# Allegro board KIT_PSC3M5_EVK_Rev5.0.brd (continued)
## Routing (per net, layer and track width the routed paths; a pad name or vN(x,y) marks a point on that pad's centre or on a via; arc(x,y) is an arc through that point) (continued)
USB_V_SENSE: length 5.2
  TOP w0.157: U2.19 92.66,35.27 92.89,35.05 v1(92.89,33.3)
  BOTTOM w0.157: R81.2 R79.2 94.13,33.81 93.62,33.3 v1(92.89,33.3)
USER_SWITCH: length 71.6
  TOP w0.178: R158.1 98.44,44.26 v1(98.63,44.45) ; SW2.B v1(44.53,57.81)
  L04_SIG2 w0.178: v1(44.53,57.81) 47.93,57.81 v1(50.93,54.81)
  BOTTOM w0.178: v1(50.93,54.81) 56.11,54.81 58.68,57.39 62.63,57.39 64.08,55.94 96.16,55.94 98.63,53.47 v1(98.63,44.45) ; R44.2 43.08,57.91 43.13,57.86 C43.1 44.48,57.86 v1(44.53,57.81)
VAREF_EXT: length 8.1
  TOP w0.292: 58.55,32.66 58.64,32.76 U1.65
  TOP w0.381: 58.55,32.66 58.24,32.36 C37.1 57.3,31.44 v1(56.79,31.95)
  BOTTOM w0.508: v1(56.79,31.95) 56.54,31.95 56.03,31.45 R92.2 R93.2
VBACKUP: length 5.3
  TOP w0.292: U1.11 v1(66.59,41.58)
  BOTTOM w0.508: v1(66.59,41.58) 66.49,41.68 C50.1 65.78,41.19 65.93,41.05 C53.1 R69.1
VOUT_3V3: length 27.9
  TOP w0.381: 116.71,19.41 J17.2 ; J17.2 118.65,19.41 ; J17.2 117.68,18.44 ; U9.3 70.55,25.14 ; U9.3 69.25,24.38 ; U9.3 71.85,24.38 ; U9.3 70.55,23.63 ; C97.1 76.03,23.1 ; C97.1 75.31,23.77 ; C97.1 74.59,23.1 ; C98.1 73.41,23.92 ; C98.1 72.46,23.12 ; C98.1 74.35,23.12
  TOP w1.016: v1(78.41,22.86) v1(77.44,22.86)
  L03_SIG1 w0.381: 117.68,18.44 J17.2 ; J17.2 118.65,19.41 ; J17.2 116.71,19.41
  L03_SIG1 w1.016: TP10.1 46.74,19.81 46.76,19.79
  BOTTOM w0.305: U5.1 86.61,32.03 C61.1
  BOTTOM w0.381: 87.37,32.26 C61.1 86.84,32.75 ; 72.05,17.38 Q7.1 72.51,16.97 ; 73.93,15.84 Q5.D ; Q5.D 73.26,16.46 ; Q5.D 73.93,17.08 ; 73.64,13.79 R141.1 ; R141.1 74.31,13.07 ; R141.1 74.31,14.51 ; v1(125.43,19.18) 125.49,19.11 R116.1 ; 77.78,33.08 R156.2 77.06,32.42
  vias: v1(52.1,24.16) v1(52.1,22.25) v1(53.11,23.27) v1(54,24.16) v1(54,22.25) v1(73,13.16) v1(73.3,13.74) v1(73.66,12.85) v1(78.16,33.05) v1(78.44,32.39) v1(87.66,31.19) v1(87.66,30.56)
VOUT_5V0: length 41
  TOP w0.292: U4.3 39.41,14.08
  TOP w0.381: 69.25,19.3 U9.1 ; U9.1 71.85,19.3 ; U9.1 70.55,18.55 ; 74.15,18.44 C95.1 ; C95.1 74.68,17.94 ; C95.1 75.2,18.44 ; 57.49,10.57 TP12.1 58.57,11.64 ; 40.29,13.24 C41.2 39.52,13.97 39.41,14.08 ; 72.62,18.44 C96.1 ; C96.1 73.68,18.44 ; C96.1 73.15,17.94
  L04_SIG2 w0.508: v1(92.61,16.69) 91.49,17.81 90.07,17.81 v1(89.23,18.64) 89.08,18.8 89.08,22.68 v1(89.43,23.04)
  BOTTOM w0.381: C83.1 90.17,21.81 ; C83.1 89.64,21.31 ; C83.1 90.7,21.31 ; C86.1 86.87,22.39 ; C86.1 85.92,21.6 ; C86.1 87.81,21.6 ; 83.63,13.23 R143.1 ; R143.1 82.94,14.15 ; R143.1 83.63,15.07 ; R123.1 89.29,18.59 v1(89.23,18.64) 89.23,18.36 C91.1 ; 81.26,17.45 Q6.1 ; Q6.1 81.72,17.86 ; Q6.1 82.19,17.45 ; C85.1 89.49,21.45 ; C85.1 88.77,22.12 ; C85.1 88.05,21.45 ; C87.1 84.71,22.39 ; C87.1 83.77,21.6 ; C87.1 85.65,21.6 ; C88.1 83.23,21.46 ; C88.1 82.43,22.41 ; C88.1 82.43,20.52 ; R126.1 v1(92.61,16.69) ; 91,21.35 U8.7 ; 91.05,21.58 U8.8 ; 83.02,16.99 Q4.D ; Q4.D 83.68,16.37 ; Q4.D 83.68,17.61
  vias: v1(74.42,17.78) v1(75.06,17.78) v1(75.44,18.42)
VREFH: length 25.8
  TOP w0.381: 65.02,57.98 J3.8 ; J3.8 66.1,59.05 ; J3.8 65.02,60.13 ; J3.8 63.95,59.05
  TOP w0.508: v1(63.78,10.57) 64.13,10.22 v1(64.64,10.22) 65.91,10.22 69.85,6.27 69.85,4.5 70.54,3.81 77.47,3.81 J24.15
  L04_SIG2 w0.635: v1(55.91,28.22) v1(56.67,28.22)
  BOTTOM w0.381: 56.75,29.37 R92.1 56.03,28.71
VTARG_DEBUG: length 14.9
  TOP w0.381: 124.95,44.32 J11.1 ; J11.1 126.36,43.72 ; J11.1 127.78,44.32
  L05_PWR w0.381: 109.57,38.61 J14.1 108.33,37.86
  BOTTOM w0.381: R147.2 65.92,12.45 ; C52.1 125.73,41.07 ; C52.1 125.73,40.01 ; C52.1 125.23,40.54 ; Q9.4 61.17,14.07 v1(61.34,13.89) ; 66.15,13.54 Q8.S ; Q8.S 66.82,14.16 ; Q8.S 66.15,14.78 ; 125.18,41.96 D1.K ; D1.K 125.7,41.35 ; D1.K 125.7,42.57
  BOTTOM w0.508: R60.2 v1(117.02,44.22) ; R52.2 v1(117.02,48.16) ; R59.2 v1(117.02,45.87)
  vias: v1(66.52,12.34) v1(66.83,12.88) v1(124.38,43.1) v1(124.89,43.43) v1(124.89,42.72)
VTARG_MEAS: length 3
  TOP w0.191: v1(93.24,40.92) 92.79,40.47 U2.32
  BOTTOM w0.381: R66.2 R67.2 94.22,40.92 v1(93.24,40.92)
VTARG_REF: length 62.1
  TOP w0.762: R41.1 84.94,24.37 v1(84.94,23.9) ; LED1.A v1(26.85,55.93) ; LED2.A v1(26.82,52.63)
  L03_SIG1 w1.016: v1(110.52,25.55) v1(110.52,24.54) 110.52,14.88 115.34,10.06 123.93,10.06 v1(125.27,11.4)
  L05_PWR w0.381: 70.55,10.79 J1.7 ; J1.7 71.63,9.72 ; J1.7 72.71,10.79
  BOTTOM w0.229: U5.4 83.19,32.03
  BOTTOM w0.381: 71.63,9.72 J1.7 ; J1.7 71.63,11.87 ; J1.7 72.71,10.79 ; J1.7 70.55,10.79 ; 63.75,11.73 R147.1 ; R147.1 64.42,12.45 ; R147.1 63.75,13.16 ; R128.1 v1(52.46,18.17) ; R57.2 50.47,48.54 v1(50.7,48.77) ; 62.32,15.55 Q9.1 62.79,15.14 ; C58.1 82.68,33.07 ; C58.1 v1(82.17,33.91) ; C58.1 82.17,32.54 ; v1(125.27,11.4) R150.2 125.27,12.88 125.36,12.98 Q10.G ; 64.15,14.49 Q8.D ; Q8.D 64.15,15.73 ; Q8.D 63.48,15.11 ; R50.2 87.63,49.07 v1(87.4,49.3) ; v1(94.39,43.31) 94.23,43.15 R66.1 ; R76.1 v1(74.45,34.57) ; R64.2 v1(49.56,42.99) ; U5.4 83.73,32.39 ; R73.1 v1(74.57,36.09) ; R153.1 v1(52.46,8.39) ; v1(85.24,49.3) 85.01,49.07 R51.2 ; R61.1 v1(85.98,45.24)
  BOTTOM w0.508: v1(31.39,16.66) R131.2 v1(32.3,17.67) ; R43.1 v1(51.59,63.27) ; v1(72.03,28.47) 72.26,28.24 R107.2
  vias: v1(64.16,11.46) v1(64.8,11.46) v1(82.83,33.93)
VTARG_REF_EN: length 5.6
  BOTTOM w0.381: R86.2 80.14,30.48 79.22,31.4
  BOTTOM w0.635: R157.1 R156.1 79.03,31.58 79.22,31.4
WCO_IN: length 5.1
  TOP w0.178: R22.1 72.43,42.84 72.17,42.58 U1.13
WCO_OUT: length 6.6
  TOP w0.178: R26.1 73.57,41.29 72.78,42.08 U1.12
XRES_L_MCU: length 335.3
  TOP w0.178: v1(102.86,44.45) R25.1 104.67,43.43 104.93,43.69 J14.10 ; J11.10 v1(120.73,49.4) ; SW1.A v1(32.38,24.43) 31.52,25.3 11.46,25.3 J16.2 ; U1.8 68.99,40.08 69.6,39.47 v1(69.62,39.47)
  L03_SIG1 w0.157: v1(120.73,49.4) 120.73,50.6 118.11,53.21 105.36,53.21 102.86,50.71 v1(102.86,44.45) ; J1.6 72.44,9.07 57.91,9.07 56.72,10.26 15.77,10.26 J18.3 9.53,16.51 J16.2 ; v1(69.62,39.47) 68.28,39.47 67.55,40.2 58.74,40.2 v1(58.19,39.65)
  L04_SIG2 w0.157: v1(102.86,44.45) 98.95,48.36 83.26,48.36 82.09,49.53 76,49.53 74.57,48.11 71.88,48.11 69.42,45.64 69.42,39.67 v1(69.62,39.47) 74.9,39.47 81.28,33.1 84.81,33.1 85.42,32.49 88.44,32.49 89.43,31.5 89.43,25.81 85.78,22.15 83.85,22.15 78.26,16.56 78.26,14.88 J1.6 ; J5.30 72.42,63.53 60.86,63.53 56.9,59.56 56.9,52.98 54.1,50.19 54.1,42.21 56.67,39.65 v1(58.19,39.65) ; J16.2 9.53,33.66 15.74,39.87 15.74,47.48 9.55,53.67 9.55,58.93 10.79,60.17 J6.3
  BOTTOM w0.178: C67.1 31.58,25.23 31.65,25.3 R109.2 32.28,24.54 v1(32.38,24.43)
N22087450: length 2.3
  TOP w0.191: U2.53 83.64,40.87 83.49,40.72
  TOP w0.381: 83.49,40.72 C12.1
N22087778: length 2.1
  TOP w0.191: U2.42 88.69,42.84 88.72,42.88
  TOP w0.381: 88.72,42.88 89.15,43.31 C5.1
N22087991: length 4
  TOP w0.114: U2.22 92.76,36.47 92.84,36.56 92.94,36.56 93.91,35.59 94.23,35.59 v1(94.51,35.31)
  BOTTOM w0.114: R75.2 95.33,35.27 95.01,35.6 94.8,35.6 v1(94.51,35.31)
N22087993: length 4
  TOP w0.114: U2.23 92.75,36.87 92.83,36.79 93.03,36.79 94.01,35.81 94.21,35.81 v1(94.51,36.12)
  BOTTOM w0.114: R72.2 95.33,36.18 94.98,35.83 94.8,35.83 v1(94.51,36.12)
N22088003: length 2.1
  TOP w0.191: U2.31 93.03,40.07
  TOP w0.381: 93.03,40.07 93.24,40.28 C13.1
N22088231: length 2.5
  TOP w0.178: LED3.A v1(114.39,25.55)
  BOTTOM w0.178: R106.1 114.55,25.71 v1(114.39,25.55)
N22092982: length 7.5
  L04_SIG2 w0.508: v1(65.3,15.27) 64.59,15.27 62.89,13.56 v1(62.89,12.85)
  BOTTOM w0.381: Q9.3 62.32,13.68 62.15,13.51 R146.1 62.74,12.7 v1(62.89,12.85) ; v1(65.3,15.27) 65.3,15.68 65.68,16.06 Q8.G
N22093014: length 3.2
  BOTTOM w0.292: R142.2 59.66,14.61 Q9.5 Q9.2
N22093052: length 1.4
  BOTTOM w0.292: R138.1 59.58,15.14 Q9.6
N22129895: length 6.6
  TOP w0.178: Y2.2 78.73,40.85 C10.2 76.68,40.85 76.35,41.17 76.35,42.32 75.21,43.46 R22.2
N22129929: length 4.6
  TOP w0.178: R18.1 74.96,45.36 C7.2 77.38,45.17 Y1.3
N22129931: length 5.1
  TOP w0.178: Y1.1 77.75,47.73 C3.1 74.96,47.14 R14.2
N22129945: length 4.1
  TOP w0.178: R26.2 75.72,40.54 76.61,39.65 C16.2 78.73,39.65 Y2.1
N22154314: length 2.3
  TOP w0.292: J15.A5 v1(121.57,28.6)
  BOTTOM w0.292: v1(121.57,28.6) 121.55,28.57 R99.1
N22154327: length 2.4
  TOP w0.292: J15.B5 v1(121.11,31.6)
  BOTTOM w0.292: v1(121.11,31.6) 120.59,31.6 R83.1
N22156925: length 6.2
  BOTTOM w0.33: 93.75,22.73 93.46,22.45 U8.11
  BOTTOM w0.381: 94.46,23.36 L1.1 ; L1.1 94.46,27.49 ; L1.1 95.23,25.43
N22156929: length 6.1
  BOTTOM w0.33: U8.9 92.46,22.55 92.25,22.76
  BOTTOM w0.381: 90.7,25.43 L1.2 ; L1.2 91.46,23.36 ; L1.2 91.46,27.49
N22157101: length 2.8
  BOTTOM w0.254: U8.14 94.97,20.58 95.22,20.32 95.22,19.74 95.74,19.22 R121.1
N22157103: length 5.7
  TOP w0.191: v1(93.6,16.15) 93.62,16.13 TP11.1
  BOTTOM w0.216: R126.2 93,18.18 93.22,17.96 93.22,16.53 v1(93.6,16.15)
  BOTTOM w0.254: R126.2 92.61,18.57 93.21,19.17 U8.2
N22157131: length 2.6
  BOTTOM w0.254: U8.1 93.71,18.77 93.8,18.68 R125.2 R124.2
N22157141: length 2.1
  BOTTOM w0.254: U8.3 92.71,19.33 91.52,18.13 C90.1
N22157156: length 5.6
  BOTTOM w0.254: U8.5 91.4,20.08 91.21,19.89 91.21,19.3 90.67,18.76 90.67,17.95 90.46,17.74 R123.2 R134.2
  BOTTOM w0.381: R134.2 89.01,16.81 88.93,16.89 88.83,16.89 C91.2
N22173555: length 5.2
  TOP w0.178: R35.1 36.57,34.48 C25.2 38.12,34.48 R36.2 40.26,34.47 TP5.1
N22173666: length 5.4
  TOP w0.178: C1.2 35.2,53.98 R5.1 R6.2 37.11,53.89 TP3.1
N22184104: length 7.2
  L04_SIG2 w0.508: v1(84.61,18.19) 82.19,15.77 v1(82.19,15.14)
  BOTTOM w0.292: 81.72,15.9 Q6.3
  BOTTOM w0.381: 81.72,15.9 81.55,15.73 R139.1 v1(82.19,15.14)
  BOTTOM w0.508: v1(84.61,18.19) 84.85,17.94 Q4.G
N22184124: length 8.6
  L04_SIG2 w0.508: v1(76.84,17.92) 75.2,16.28 74.19,16.28 v1(72.8,14.88)
  BOTTOM w0.292: 72.05,15.27 Q7.3
  BOTTOM w0.381: v1(72.8,14.88) 72.57,14.66 R140.1 72,15.22 72.05,15.27
  BOTTOM w0.508: v1(76.84,17.92) 76.44,17.92 Q5.G
N22184135: length 3.2
  BOTTOM w0.292: R133.2 79.22,16.92 Q6.5 Q6.2
N22184141: length 3.3
  BOTTOM w0.292: R135.2 69.69,16.43 Q7.5 Q7.2
N22184147: length 1.3
  BOTTOM w0.292: R127.1 79.38,17.48 79.4,17.45 Q6.6
N22184151: length 1.3
  BOTTOM w0.292: Q7.6 69.5,16.97 69.37,16.84 R130.1
N22185312: length 11.1
  TOP w0.178: v1(123.16,57.12) 121.85,55.82 R2.1
  BOTTOM w0.178: v1(123.16,57.12) C42.1 123.16,61.19 R1.2
N22190096: length 120.3
  TOP w0.203: v1(52.98,65.81) 52.81,65.99 SW4.A
  L04_SIG2 w0.157: v1(103.02,62.26) 104.42,62.26 106.2,60.48 106.2,57.05 105.31,56.16 105.31,27.08 111.79,20.6 111.79,9.04 109.6,6.86 108.46,6.86 J24.38
  BOTTOM w0.178: v1(103.02,62.26) 102.51,62.76 59.84,62.76 56.23,66.38 R160.1 53.55,66.38 v1(52.98,65.81)
  BOTTOM w0.203: R43.2 52.97,65.8 v1(52.98,65.81)
N22190335: length 2.5
  TOP w0.178: LED2.K v1(29.75,51.33)
  BOTTOM w0.178: v1(29.75,51.33) 29.92,51.5 R46.1
N22190371: length 2.2
  TOP w0.178: LED1.K v1(29.75,57.16)
  BOTTOM w0.178: v1(29.75,57.16) 29.95,56.97 R45.1
N22190519: length 3.3
  BOTTOM w0.178: R128.2 53.31,14.19 J19.1
N22190521: length 3.3
  BOTTOM w0.178: J22.1 53.31,4.41 R153.2
N22190557: length 3.3
  BOTTOM w0.178: J19.3 48.1,14.23 R129.1
N22190561: length 3.3
  BOTTOM w0.178: R154.1 48.1,4.45 J22.3
N22191822: length 3.8
  BOTTOM w0.305: U5.3 83.06,31.53 82.92,31.67 R155.2 81.31,31.67 C62.1 81.28,31.04 81.32,30.99 R86.1
N22248472: length 6.9
  TOP w0.178: J13.S R32.1
N22248626: length 8.9
  TOP w0.178: R4.1 33.68,57.18 35.08,58.57 J7.S
N22257092: length 12.2
  TOP w0.178: v1(32.95,11.68) 32.95,12.37 v1(34.44,13.87) 34.66,14.08 U4.6 ; v1(33,8.79) 33,6.43 32.13,5.56 J23.1
  BOTTOM w0.178: v1(32.95,11.68) C94.2 33,10.77 R152.1 v1(33,8.79) ; R144.1 v1(34.44,13.87)
N22257130: length 12.1
  TOP w0.178: v1(33.91,11.68) 33.91,12.19 v1(34.44,12.73) 34.44,13.06 34.81,13.43 U4.7 ; v1(33.85,8.79) 33.85,8.08 34.03,7.9 34.42,7.9 34.59,7.72 34.59,7.37 34.42,7.19 34.03,7.19 33.85,7.01 33.85,6.38 34.67,5.56 J23.2
  BOTTOM w0.178: v1(33.85,8.79) R152.2 33.85,10.77 C94.1 v1(33.91,11.68) ; R145.2 v1(34.44,12.73)
N22257140: length 2.3
  BOTTOM w0.178: R144.2 R145.1 C93.1
N22258155: length 2.1
  TOP w0.178: U4.1 39.08,12.78 v1(39.52,12.34)
  BOTTOM w0.178: R149.1 v1(39.52,12.34)
N22258259: length 2.2
  TOP w0.178: v1(39.52,15.01) 39.24,14.73 U4.4
  BOTTOM w0.178: R137.1 39.9,15.39 v1(39.52,15.01)
N22258799: length 5.3
  BOTTOM w0.381: Q1.S 104.64,30.95 ; Q1.S 104.02,31.42 ; Q1.S 104.02,30.48 ; 103.97,28.44 Q3.S 104.44,27.82 ; 107.74,30.73 Q2.S 107.12,31.2 ; 105.41,31.24 R84.2 ; R84.2 105.94,30.74 ; R84.2 106.47,31.24
N22258824: length 4
  BOTTOM w0.381: R98.2 102.05,29.98 ; R98.2 102.47,29.49 ; R98.2 102.05,29 ; 102.54,27.82 Q3.G 102.07,28.44 ; Q1.D 102.64,31.9 ; Q1.D 102.02,32.37 ; Q1.D 102.02,31.43
N22258828: length 7.9
  BOTTOM w0.381: D2.K 106.1,33.1 105.94,32.94 R84.1 ; D2.K 105.26,34.44 ; D2.K 106.1,35.66 ; R84.1 105.34,32.32 104.8,32.85 Q1.G ; R84.1 106.47,32.32 ; Q1.G 104.02,33.32 ; Q1.G 104.02,32.38
N22307724: length 2.2
  TOP w0.178: LED4.K 124.78,16.83 v1(124.71,16.76)
  BOTTOM w0.178: Q10.D v1(124.71,16.76)
N223077121: length 2.4
  TOP w0.178: LED4.A v1(126.58,19.25)
  BOTTOM w0.178: R116.2 126.57,18.59 126.58,18.59 v1(126.58,19.25)

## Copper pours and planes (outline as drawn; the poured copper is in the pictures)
GND_EARTH on BOTTOM: 128.93,36.73 127.91,37.74 122.45,37.74 121.64,36.93 121.64,33.22 122.33,32.54 122.33,23.65 121.95,23.27 121.95,20.85 122.2,20.6 128.42,20.6 128.93,21.11
GND_SIGNAL on TOP (solid shape): 16.73,50.48 15.02,50.48 15.02,54.36 16.73,54.36
GND_SIGNAL on TOP (solid shape): 16.73,1.2 15.02,1.2 15.02,5.08 16.73,5.08
GND_SIGNAL on TOP (solid shape): 121.92,33.32 123.01,33.32 123.16,33.17 123.16,32.87 123.11,32.82 120.8,32.82 120.52,33.1 120.52,33.58 120.68,33.73 121.51,33.73
GND_SIGNAL on TOP (solid shape): 123.16,26.82 123.16,26.47 123.06,26.37 122.02,26.37 121.74,26.09 120.93,26.09 120.85,26.16 120.85,26.82 120.93,26.9 123.09,26.9
GND_SIGNAL on TOP: 128.98,2.54 128.54,1.46 127.46,1.02 2.54,1.02 1.46,1.46 1.02,2.54 1.02,67.46 1.46,68.54 2.54,68.98 127.46,68.98 128.54,68.54 128.98,67.46 ; 50 cut-outs
GND_SIGNAL on BOTTOM: 128.98,2.54 128.54,1.46 127.46,1.02 2.54,1.02 1.46,1.46 1.02,2.54 1.02,67.46 1.46,68.54 2.54,68.98 127.46,68.98 128.54,68.54 128.98,67.46 ; 21 cut-outs
GND_SIGNAL on L02_GND: 128.98,2.54 128.54,1.46 127.46,1.02 2.54,1.02 1.46,1.46 1.02,2.54 1.02,67.46 1.46,68.54 2.54,68.98 127.46,68.98 128.54,68.54 128.98,67.46
VCC_IN on BOTTOM: 94.08,20.98 96.82,20.98 97.13,21.29 103.35,21.29 104.37,20.27 104.37,18.39 104.09,18.11 97.08,18.11 96.65,18.54 95,18.54 94.64,18.19 94.64,16.41 95.15,15.9 101.88,15.9 103.28,14.5 107.21,14.5 107.85,15.14 107.85,23.52 107.34,24.03 97.28,24.03 95.73,22.48 94.41,22.48 94.08,22.15
VDD_POT on BOTTOM: 114.71,54.64 122.2,62.13 126.01,62.13 127.03,63.14 127.03,64.8 126.19,65.63 118.69,65.63 112.52,59.46 112.52,54.79 112.67,54.64
VDDA on BOTTOM: 111.71,60.45 109.93,60.45 109.42,59.94 109.42,54.86 109.8,54.48 111.84,54.48 112.09,54.74 112.09,60.07
VDDA on BOTTOM: 55.02,29.74 53.49,29.74 53.49,28.85 53.37,28.73 44.98,28.73 44.6,29.11 44.6,41.55 44.22,41.94 40.79,41.94 40.16,41.3 40.16,26.82 41.61,25.37 54.33,25.37 55.14,26.19 55.14,29.62
VDDA on L04_SIG2: 59.97,33.93 53.75,33.93 53.24,33.43 53.24,27.84 53.49,27.58 54.89,27.58 55.14,27.84 55.14,29.11 56.92,30.89 60.1,30.89 60.6,31.39 60.6,33.3
VDDA on L05_PWR: 61.62,56.54 53.87,64.29 50.62,64.29 50.01,63.68 50.01,56.26 50.85,55.42 50.85,50.24 48.67,48.06 48.67,38.25 47.78,37.36 42.95,37.36 42.32,38 42.32,41.94 43.08,42.7 43.08,65.56 45.49,67.97 84.76,67.97 90.25,62.48 107.37,62.48 108.41,61.44 112.17,61.44 112.65,60.96 112.65,57 112.19,56.54
VDDD on L05_PWR: 42.44,57.05 39.27,57.05 38.73,56.52 38.73,35.05 31.9,28.22 31.9,26.7 32.41,26.19 35.59,26.19 42.57,33.17 56.16,33.17 62.51,39.52 70.76,39.52 71.15,39.9 71.15,41.3 69.75,42.7 58.95,42.7 53.24,36.98 43.97,36.98 42.65,38.3 42.65,56.84
VDDIO_0 on BOTTOM: 55.02,50.57 53.75,50.57 53.62,50.44 53.62,43.46 52.48,42.32 50.19,42.32 49.81,41.94 49.81,40.92 57.45,40.92 59.08,42.55 68.61,42.55 69.52,43.46 72.24,43.46 73.69,44.91 73.69,46.76 73.3,47.14 56.29,47.14 55.4,48.03 55.4,50.19
VIN on TOP: 99.97,17.3 98.7,17.3 98.32,16.92 98.32,13.87 98.58,13.61 100.23,13.61 100.48,13.87 100.48,16.79
VIN on BOTTOM: 117.17,9.75 114.71,9.75 114.1,10.36 114.1,15.72 113.61,16.21 112.47,16.21 111.58,17.09 109.45,17.09 109.27,16.92 109.27,14.78 108.61,14.12 102.64,14.12 101.37,15.39 99.21,15.39 98.7,14.88 98.7,12.34 99.09,11.96 110.44,11.96 110.9,11.51 110.9,5.36 111.71,4.55 117.32,4.55 117.63,4.85 117.63,9.3
VIN_EXP on TOP: 61.42,13.41 59.08,11.07 59.08,4.34 59.72,3.71 62.38,3.71 63.02,4.34 63.02,9.93 63.88,10.8 73.15,10.8 79.68,17.32 86.23,17.32 87.58,15.98 87.58,13.28 87.12,12.83 86.18,12.83 85.5,12.14 85.5,9.68 85.75,9.42 89.81,9.42 90.22,9.83 90.22,11.61 91.59,12.98 96.8,12.98 97.43,13.61 97.43,20.22 96.75,20.9 79.2,20.9 71.7,13.41
(no net) on L03_SIG1: 128.98,2.54 128.54,1.46 127.46,1.02 2.54,1.02 1.46,1.46 1.02,2.54 1.02,67.46 1.46,68.54 2.54,68.98 127.46,68.98 128.54,68.54 128.98,67.46 ; 93 cut-outs
(no net) on L04_SIG2: 128.98,2.54 128.54,1.46 127.46,1.02 2.54,1.02 1.46,1.46 1.02,2.54 1.02,67.46 1.46,68.54 2.54,68.98 127.46,68.98 128.54,68.54 128.98,67.46 ; 73 cut-outs
ARD_A4 on TOP (solid shape): 6.57,50.48 4.86,50.48 4.86,54.36 6.57,54.36
ARD_A4 on TOP (solid shape): 6.57,1.2 4.86,1.2 4.86,5.08 6.57,5.08
ARD_A5 on TOP (solid shape): 9.11,50.48 7.4,50.48 7.4,54.36 9.11,54.36
ARD_A5 on TOP (solid shape): 9.11,1.2 7.4,1.2 7.4,5.08 9.11,5.08
HDR_3V3 on TOP (solid shape): 19.27,50.48 17.56,50.48 17.56,54.36 19.27,54.36
HDR_3V3 on TOP (solid shape): 19.27,1.2 17.56,1.2 17.56,5.08 19.27,5.08
HDR_3V3 on BOTTOM: 70.64,16.03 69.62,16.03 69.49,15.9 69.49,14.63 69.75,14.38 70.38,14.38 70.64,14.63
HDR_3V3 on BOTTOM: 76.66,16.28 75.72,16.28 75.36,15.93 75.36,14.61 75.23,14.48 75.23,12.37 75.44,12.17 75.44,9.55 75.69,9.3 77.75,9.3 78,9.55 78,14.94
HDR_3V3 on L03_SIG1: 77.34,9.83 75.64,9.83 75.23,10.24 75.23,13.34 74.07,14.5 69.75,14.5 69.37,14.88 69.37,17.17 70.51,18.31 75.97,18.31 77.72,16.56 77.72,10.21
HDR_3V3 on L04_SIG2: 26.06,24.79 22,24.79 20.98,23.77 20.98,21.49 24.54,17.93 24.54,13.74 17.17,6.38 17.17,4.22 17.93,3.45 25.93,3.45 27.46,4.98 27.46,23.39
HDR_3V3 on L05_PWR: 108.13,66.22 122.12,66.22 128.93,59.41 128.93,4.42 125.53,1.02 4.62,1.02 2.31,3.33 2.31,52.86 5.31,55.85 19.25,55.85 19.84,55.27 19.84,33.43 12.6,26.19 12.6,17.42 23.27,6.76 73.71,6.76 74.8,7.85 74.8,11.46 75.44,12.09 80.04,12.09 80.67,11.46 80.67,7.75 81.43,6.99 123.09,6.99 125.07,8.97 125.07,34.65 125.6,35.18 125.6,53.64 117.37,61.87 108.61,61.87 107.77,62.71 107.77,65.86
HDR_5V0 on TOP (solid shape): 4.03,50.48 2.32,50.48 2.32,54.36 4.03,54.36
HDR_5V0 on TOP (solid shape): 4.03,1.2 2.32,1.2 2.32,5.08 4.03,5.08
HDR_5V0 on TOP: 72.8,8.03 73.43,7.39 82.04,7.39 83.03,8.38 83.03,11.81 84.45,13.23 86.92,13.23 87.15,13.46 87.15,15.67 85.93,16.89 76.76,16.89 72.8,12.93
HDR_5V0 on BOTTOM: 85.5,16.41 85.17,16.08 85.17,14.5 85.09,14.43 85.09,13.08 84.53,12.52 81.86,12.52 80.54,13.84 80.54,16.41 80.29,16.66 79.27,16.66 78.64,16.03 78.64,9.17 79.15,8.66 87.78,8.66 88.29,9.17 88.29,16.15 88.04,16.41
HDR_5V0 on L03_SIG1: 1.73,56.03 3.84,56.03 4.52,55.35 4.52,52.63 8.86,48.29 22.5,48.29 23.65,47.14 23.65,44.88 21.72,42.95 7.77,42.95 5.16,40.34 5.16,17.48 4.11,16.43 4.11,3.48 4.22,3.38 8.86,3.38 9.4,3.91 9.4,8.41 10.57,9.58 75.97,9.58 76.23,9.32 76.23,7.39 75.21,6.38 48.29,6.38 43.05,1.14 2.21,1.14 1.04,2.31 1.04,55.35 ; 2 cut-outs
HDR_I2C_SCL on TOP (solid shape): 14.19,50.48 12.48,50.48 12.48,54.36 14.19,54.36
HDR_I2C_SCL on TOP (solid shape): 14.19,1.2 12.48,1.2 12.48,5.08 14.19,5.08
HDR_I2C_SDA on TOP (solid shape): 11.65,50.48 9.94,50.48 9.94,54.36 11.65,54.36
HDR_I2C_SDA on TOP (solid shape): 11.65,1.2 9.94,1.2 9.94,5.08 11.65,5.08
KP_VBUS on BOTTOM: 105.56,27.84 107.09,27.84 107.34,27.58 107.34,26.7 111.91,22.12 111.91,20.93 112.17,20.68 113.03,20.68 113.28,20.42 113.28,18.67 113.06,18.44 108.86,18.44 108.61,18.69 108.61,23.27 107.09,24.79 99.34,24.79 99.11,25.02 99.11,26.85 99.34,27.08 100.74,27.08 101.12,26.7 104.42,26.7
KP_VBUS_IN on TOP (solid shape): 123.11,32.5 123.11,32.07 123.04,31.99 120.9,31.99 120.78,32.12 120.78,32.47 120.88,32.58 123.04,32.58
KP_VBUS_IN on TOP (solid shape): 122.07,27.71 123.11,27.71 123.16,27.66 123.16,27.23 123.14,27.2 120.95,27.2 120.85,27.3 120.85,28.04 120.95,28.14 121.64,28.14
KP_VBUS_IN on BOTTOM: 108.86,30.51 116.15,30.51 118.44,28.22 121.69,28.22 121.95,27.97 121.95,26.95 121.56,26.57 116.74,26.57 115.7,27.61 111.2,27.61 109.65,26.06 108.48,26.06 108.1,26.44 108.1,29.74
KP_VBUS_IN on L05_PWR: 122.71,33.22 119.35,33.22 118.62,32.49 118.62,26.16 119.28,25.5 122.35,25.5 123.04,26.19 123.04,32.89
P3_1 on TOP (solid shape): 14.19,64.52 12.48,64.52 12.48,68.4 14.19,68.4
P3_1 on TOP (solid shape): 14.19,15.24 12.48,15.24 12.48,19.12 14.19,19.12
P3_VDD on BOTTOM: 75.82,32.26 74.17,32.26 73.91,32.51 73.91,33.53 74.17,33.78 75.95,33.78 75.95,32.39
P3_VDD on BOTTOM: 62.26,29.87 60.48,29.87 60.48,28.47 60.73,28.22 62.13,28.22 62.38,28.47 62.38,29.74
P3_VDD on BOTTOM: 64.8,39.27 63.53,39.27 63.14,38.89 63.14,37.36 63.53,36.98 64.8,36.98 65.05,37.24 65.05,39.01
P3_VDD on BOTTOM: 72.29,38.25 73.94,38.25 74.19,38 74.19,36.98 73.94,36.73 72.67,36.73 72.29,37.11
P3_VDD on BOTTOM: 74.07,49.43 72.8,49.43 72.54,49.17 72.54,47.9 72.8,47.65 74.07,47.65 74.32,47.9 74.32,49.17
P3_VDD on L03_SIG1: 72.95,37.97 74.52,37.97 75.23,37.26 75.23,35.23 75.9,34.57 83.82,34.57 83.87,34.52 84.4,34.52 85.93,32.99 87.73,32.99 92.08,28.65 113.06,28.65 119.02,22.68 119.02,21.26 118.52,20.75 115.52,20.75 109.93,26.34 86.16,26.34 82.58,29.92 76.66,29.92 72.59,33.99 72.59,37.62 ; 2 cut-outs
P3_VDD on L04_SIG2: 127.15,23.27 116.48,23.27 116.1,22.89 116.1,15.14 116.74,14.5 127.53,14.5 127.91,14.88 127.91,22.5
P3_VDD on L05_PWR: 74.32,49.43 71.78,49.43 71.53,49.17 71.53,39.78 70.89,39.14 64.92,39.14 59.97,34.19 59.97,28.73 60.6,28.09 65.43,28.09 75.72,38.38 75.72,48.03
P4_5 on TOP (solid shape): 21.81,50.48 20.1,50.48 20.1,54.36 21.81,54.36
P4_5 on TOP (solid shape): 21.81,1.2 20.1,1.2 20.1,5.08 21.81,5.08
P5LP_VDD on BOTTOM: 96.93,27.08 96.82,26.97 96.82,24.99 97.08,24.74 98.35,24.74 98.5,24.89 98.5,26.92 98.35,27.08
P5LP_VDD on L05_PWR: 97.66,24.79 101.5,24.79 106.86,30.15 106.86,46.41 107.98,47.52 115.34,47.52 115.98,48.16 115.98,54.64 115.21,55.4 97.94,55.4 95.91,53.37 95.91,43.08 95.28,42.44 93.5,42.44 92.99,42.95 92.99,43.84 92.23,44.6 83.08,44.6 81.81,43.33 81.81,35.46 82.45,34.82 87.66,34.82 87.72,34.76 90.13,34.76 91.62,33.27 91.62,30.84
P9_4 on TOP (solid shape): 16.73,64.52 15.02,64.52 15.02,68.4 16.73,68.4
P9_4 on TOP (solid shape): 16.73,15.24 15.02,15.24 15.02,19.12 16.73,19.12
PWM_SHIELD on TOP (solid shape): 24.35,50.48 22.64,50.48 22.64,54.36 24.35,54.36
PWM_SHIELD on TOP (solid shape): 24.35,1.2 22.64,1.2 22.64,5.08 24.35,5.08
SPI_CLK_ARD on TOP (solid shape): 19.27,64.52 17.56,64.52 17.56,68.4 19.27,68.4
SPI_CLK_ARD on TOP (solid shape): 19.27,15.24 17.56,15.24 17.56,19.12 19.27,19.12
SPI_MISO_ARD on TOP (solid shape): 24.35,64.52 22.64,64.52 22.64,68.4 24.35,68.4
SPI_MISO_ARD on TOP (solid shape): 24.35,15.24 22.64,15.24 22.64,19.12 24.35,19.12
SPI_MOSI_ARD on TOP (solid shape): 21.81,64.52 20.1,64.52 20.1,68.4 21.81,68.4
SPI_MOSI_ARD on TOP (solid shape): 21.81,15.24 20.1,15.24 20.1,19.12 21.81,19.12
UART_RX_0_MIK on TOP (solid shape): 6.57,64.52 4.86,64.52 4.86,68.4 6.57,68.4
UART_RX_0_MIK on TOP (solid shape): 6.57,15.24 4.86,15.24 4.86,19.12 6.57,19.12
UART_TX_0_MIK on TOP (solid shape): 9.11,64.52 7.4,64.52 7.4,68.4 9.11,68.4
UART_TX_0_MIK on TOP (solid shape): 9.11,15.24 7.4,15.24 7.4,19.12 9.11,19.12
VOUT_3V3 on TOP: 68.28,25.63 72.29,25.63 73.15,24.77 90.7,24.77 90.7,23.57 95.4,23.57 95.4,24.77 102.41,24.77 106.63,20.55 118.44,20.55 119.1,19.89 119.1,17.07 118.31,16.28 105.51,16.28 100.69,21.11 77.34,21.11 76.48,21.97 76.45,21.97 75.82,22.61 72.64,22.61 71.86,23.39 68.38,23.39 67.97,23.8 67.97,25.32
VOUT_3V3 on BOTTOM: 88.8,34.19 85.62,34.19 84.99,33.55 84.99,32.03 85.17,31.85 86.64,31.85 86.64,30.63 87.15,30.12 88.93,30.12 89.31,30.51 89.31,33.68
VOUT_3V3 on BOTTOM: 78.74,33.78 76.58,33.78 76.33,33.53 76.33,32.51 76.71,32.13 78.61,32.13 78.74,32.26
VOUT_3V3 on BOTTOM: 71.91,16.66 72.31,16.66 73.18,15.8 73.18,14.1 72.87,13.79 72.87,12.7 73.03,12.55 74.37,12.55 74.47,12.65 74.47,15.54 74.24,15.77 74.24,17.68 73.99,17.93 72.16,17.93 71.91,17.68
VOUT_3V3 on BOTTOM: 61.98,23.37 61.09,23.37 59.59,24.87 48.23,24.87 47.52,24.16 47.52,22.12 48.16,21.49 61.49,21.49 62.15,22.15 62.15,23.19
VOUT_3V3 on L03_SIG1: 61.75,24.28 58.19,24.28 57.56,24.92 49.3,24.92 48.29,23.9 48.29,20.5 44.45,20.5 44.12,20.17 44.12,19.51 44.35,19.28 48.29,19.28 48.29,13.36 50.32,11.33 73.69,11.33 74.45,12.09 74.45,13.87 74.07,14.25 69.37,14.25 66.19,17.42 62.89,17.42 62.26,18.06 62.26,23.77
VOUT_3V3 on L03_SIG1: 116.1,15.14 116.99,14.25 125.5,14.25 125.63,14.38 125.63,19.35 125.09,19.89 116.97,19.89 116.1,19.02
VOUT_3V3 on L05_PWR: 72.52,27.84 49.56,27.84 48.36,26.64 48.36,22.48 49.23,21.62 79.15,21.62 81.99,24.46 86.72,24.46 87.45,25.2 87.45,27.15 87.91,27.61 87.91,31.27 87.78,31.39 80.49,31.39 78.54,33.35 78.03,33.35
VOUT_5V0 on TOP: 61.21,13.46 59.08,11.33 59.08,10.44 58.45,9.8 42.57,9.8 39.4,12.98 39.4,13.49 39.01,13.87 38.25,13.87 38,14.12 38,14.25 38.13,14.38 42.19,14.38 44.28,16.47 66.03,16.47 66.4,16.84 66.4,19.56 66.73,19.89 71.6,19.89 72.82,18.67 75.31,18.67 75.57,18.92 75.82,18.92 76.07,18.67 76.07,18.03 71.5,13.46 ; 1 cut-out
VOUT_5V0 on BOTTOM: 82.27,23.85 89.1,23.85 90.55,22.4 91.59,22.4 91.87,22.12 91.87,20.95 83.52,20.95 83.52,18.16 84.1,17.58 84.1,13 83.95,12.85 82.85,12.85 82.73,12.98 82.73,15.72 82.35,16.1 81.56,16.1 81.41,16.26 81.41,17.04 81.15,17.3 81.15,17.78 80.52,18.42 76.2,18.42 75.31,17.53 74.3,17.53 74.17,17.65 74.17,18.92 75.11,19.86 81.58,19.86 81.79,20.07 81.79,23.37
VREFH on TOP: 57.05,28.73 55.14,28.73 51.82,25.4 48.39,25.4 48.01,25.78 48.01,28.83 48.03,28.85 48.03,39.9 48.79,40.67 48.79,43.33 54.89,49.43 54.89,50.7 55.91,51.71 62.23,51.71 66.45,55.93 66.45,59.97 65.94,60.48 64.29,60.48 63.65,59.84 63.65,57.4 60.76,54.51 54.89,54.51 52.68,52.3 52.68,50.95 46.13,44.4 46.13,22.71 47.75,21.08 54.25,21.08 55.14,21.97 55.14,25.6 57.18,27.64 57.18,28.6
VREFH on BOTTOM: 56.79,29.74 55.52,29.74 55.52,27.71 55.65,27.58 56.92,27.58 57.05,27.71 57.05,29.49
VREFH on L04_SIG2: 57.56,28.73 55.78,28.73 55.52,28.47 55.52,20.85 60.6,15.77 60.6,11.96 63.02,9.55 64.67,9.55 65.05,9.93 65.05,11.58 63.02,13.61 63.02,17.3 58.57,21.74 58.57,27.71
VTARG_DEBUG on TOP: 127.97,44.65 124.92,44.65 124.16,43.89 124.16,42.72 124.56,42.32 127.66,42.32 128.14,42.8 128.14,44.48
VTARG_DEBUG on BOTTOM: 127.56,43.76 124.23,43.76 123.77,43.31 123.77,40.06 124.21,39.62 125.83,39.62 125.98,39.78 125.98,42.37 126.24,42.62 127.56,42.62 127.74,42.8 127.74,43.59
VTARG_DEBUG on BOTTOM: 67.23,15.09 65.99,15.09 65.74,14.83 65.74,13.54 65.48,13.28 65.48,11.94 65.58,11.84 66.98,11.84 67.41,12.27 67.41,14.91
VTARG_DEBUG on L05_PWR: 124.49,48.87 117.3,48.87 116.48,48.06 116.48,46.23 115.67,45.42 110.16,45.42 107.42,42.67 107.42,29.74 111.28,25.88 111.28,21.95 105.54,16.21 61.82,16.21 60.99,15.37 60.99,12.75 61.57,12.17 73.53,12.17 73.84,12.47 80.31,12.47 80.85,11.94 111.86,11.94 118.34,18.41 118.34,33.66 121.08,36.4 123.47,36.4 125.25,38.18 125.25,48.11
VTARG_REF on BOTTOM: 83.34,34.19 82.07,34.19 81.94,34.06 81.94,32.41 82.45,31.9 83.85,31.9 83.97,32.03 83.97,33.55
VTARG_REF on BOTTOM: 62.1,14.99 62.76,14.99 63.25,14.5 63.25,10.11 64.11,9.25 72.52,9.25 72.97,9.7 72.97,11.51 72.14,12.34 67.79,12.34 66.9,11.46 65.07,11.46 64.8,11.73 64.8,15.88 64.36,16.31 62.38,16.31 62.1,16.03
VTARG_REF on L05_PWR: 58.32,42.57 65.56,49.81 74.57,49.81 76.23,48.16 76.23,38.51 68.61,30.89 68.61,28.6 69.37,27.84 71.96,27.84 75.51,31.39 87.66,31.39 88.16,30.89 88.16,27.84 84.73,24.41 82.7,24.41 79.4,21.11 32.79,21.11 29.31,24.59 29.31,65.35 27.97,66.7 17.81,66.7 17.12,66.01 17.12,61.54 20.6,58.06 20.6,33.55 13.36,26.31 13.36,17.93 23.72,7.57 30.15,7.57 72.83,7.5 73.33,8 73.33,10.92 72.59,11.66 61.62,11.66 60.6,12.67 60.6,15.52 61.62,16.54 105.18,16.54 111.02,22.38 111.02,25.55 110.77,25.81 103.28,25.81 101.24,23.77 97.82,23.77 91.97,29.62 91.97,29.87 91.21,30.63 91.21,33.17 89.94,34.44 82.19,34.44 81.43,35.2 81.43,43.46 82.96,44.98 92.61,44.98 93.37,44.22 93.37,43.21 93.62,42.95 94.89,42.95 95.15,43.21 95.15,53.59 92.58,56.16 60.35,56.16 52.86,63.65 50.95,63.65 50.57,63.27 50.57,56.36 51.28,55.65 51.28,50.19 49.17,48.08 49.17,42.95 49.56,42.57
XRES_L_MCU on TOP (solid shape): 11.65,64.52 9.94,64.52 9.94,68.4 11.65,68.4
XRES_L_MCU on TOP (solid shape): 11.65,15.24 9.94,15.24 9.94,19.12 11.65,19.12
N22156925 on BOTTOM: 96.04,27.84 94.26,27.84 93.9,27.48 93.9,23.32 93.32,22.73 93.32,21.18 93.45,21.06 93.62,21.06 93.73,21.16 93.73,22.35 94.06,22.68 95.4,22.68 96.42,23.7 96.42,27.46
N22156929 on BOTTOM: 92.1,27.84 90.07,27.84 89.81,27.58 89.81,23.77 90.91,22.68 91.69,22.68 92.18,22.2 92.18,21.11 92.33,20.95 92.53,20.95 92.61,21.03 92.61,22.86 92.3,23.16 92.3,27.64
N22258799 on BOTTOM: 107.98,31.65 104.04,31.65 103.66,31.27 103.66,27.71 103.91,27.46 104.8,27.46 105.31,27.97 105.31,29.62 106.07,30.38 107.85,30.38 108.1,30.63 108.1,31.52
N22258824 on BOTTOM: 102.77,32.66 101.83,32.66 101.63,32.46 101.63,27.71 101.88,27.46 102.77,27.46 103.02,27.71 103.02,32.41
N22258828 on BOTTOM: 106.32,35.97 104.29,35.97 103.63,35.31 103.63,32.56 104.17,32.03 106.45,32.03 106.71,32.28 106.71,35.59

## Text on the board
BOTTOM: BOTTOM SIDE
Ref Des/Assembly Bottom: ASSEMBLY BOTTOM
Board Geometry/Soldermask Bottom: SOLDERMASK BOTTOM
Ref Des/Silkscreen Bottom: J8 | J21 | 1 | J6 | J18 | J12 | J16 | J7 | J13 | GND | J24 | J3 | J1 | J2 | J14 | J4 | J5 | J9 | J17 | POT | VDD.POT | 3 | 5 | VOUT.3V3 | P3.VDD | SCL | SDA | NC | D13 | REF | VTARG | D12 | XRES | D11 | V3 | . | D10 | V5 | 0 | D9 | D8 | D7 | VIN | D6 | D5 | A0 | A1 | D4 | D3 | A2 | A3 | D2 | D1 | A4 | D0 | A5 | A6 | (B7) | A7 | CANL | CANH | P9.0 | P9.2 | VREF | AREF | P7.0 | P7.2 | P7.1 | P7.3 | P4.3 | P7.6 | P3.0 | P4.2 | P4.1 | P6.0 | P4.0 | P6.1 | P3.3 | P3.2 | (RX) | (TX) | P6.3 | P6.2 | UART | I2C SDA | I2C SCL | P12.6 | P12.7 | P12.1 | P12.0 | PIN | P1.0 | P1.1 | P0.1 | P0.0 | PSOC C3 | FUNCTION | ECO.IN | ECO.OUT | WCO.IN | WCO.OUT | VTARG.REF | LED1 | LED2 | O | R | P8.4 | P8.5 | SW4 | SW2 | P5.0 | SW1 | P2.0 | KITPROG3 | SILKSCREEN BOTTOM
TOP: TOP SIDE
Ref Des/Assembly Top: ASSEMBLY TOP
Board Geometry/Soldermask Top: SOLDERMASK TOP
Ref Des/Silkscreen Top: GND | 1 | VOUT.3V3 | 3 | VOUT.5V0 | EXT.CLK | ECO | VCC.IN | TP9 | P3.VDD | 5 | KP.VBUS.IN | - | 7V-12V | + | USER LEDs | CAN FD | XRES | USER BTN1 | USER BTN2 | DFU SWITCH | NOR FLASH | KITPROG3 | MODE SELECT | MCU DEBUG | AND TRACE | STATUS | POT | MEASUREMENT | CURRENT | MCU PROG/DEBUG | KITPROG3 USB | POWER | 5V | AN1 | RX | AN | PWM | TX | AN2 | GPIO | RST | SDA | CS | SCL | SCK | mikro | MISO | BUS | 3V3 | CLK | MOSI | INT | S2GO1 | S2GO2 | PSOC CONTROL C3M5 | EVALUATION KIT | SILKSCREEN TOP
L02_GND: L02_GND
L03_SIG1: L03_SIG1
L04_SIG2: L04_SIG2
L05_PWR: L05_PWR
DIMENSION: Date code & UL logo | SOLDERPASTE TOP
PAGE_OUTLINE: SOLDERPASTE BOTTOM
User.6: GOLDMASK TOP
User.7: GOLDMASK BOTTOM
User.19: 90E | DIFF | IMP | OHMS | --- | ---- | WIDTH/SPACE | TRACE | LAYER | REF
User.22: 09/10/24 | PSOC Control C3M5 | Evaluation Kit
User.23: 2
User.45: FIGURE | FINISHED_SIZE | 7.87 | 9.839 | 27.559 | 29.921 | 39.37 | 40.157 | 40.161 | 51.181 | 61.024 | 25.591 | 55.118x23.622 | 66.929x23.622 | 70.0x43.311 | DRILLED_SIZE | - | DRILL CHART: TOP to BOTTOM | ALL UNITS ARE IN MILS | FINISHED_TOL | +3.0/-3.0 | +1.969/-9.839 | +2.0/-2.0 | DRILLED_TOL | PLATED | NON-PLATED | QTY | 611 | 35 | 20 | 3 | 52 | 80 | 59 | 10 | 2 | 1 | 882 | TOTAL HOLES:
